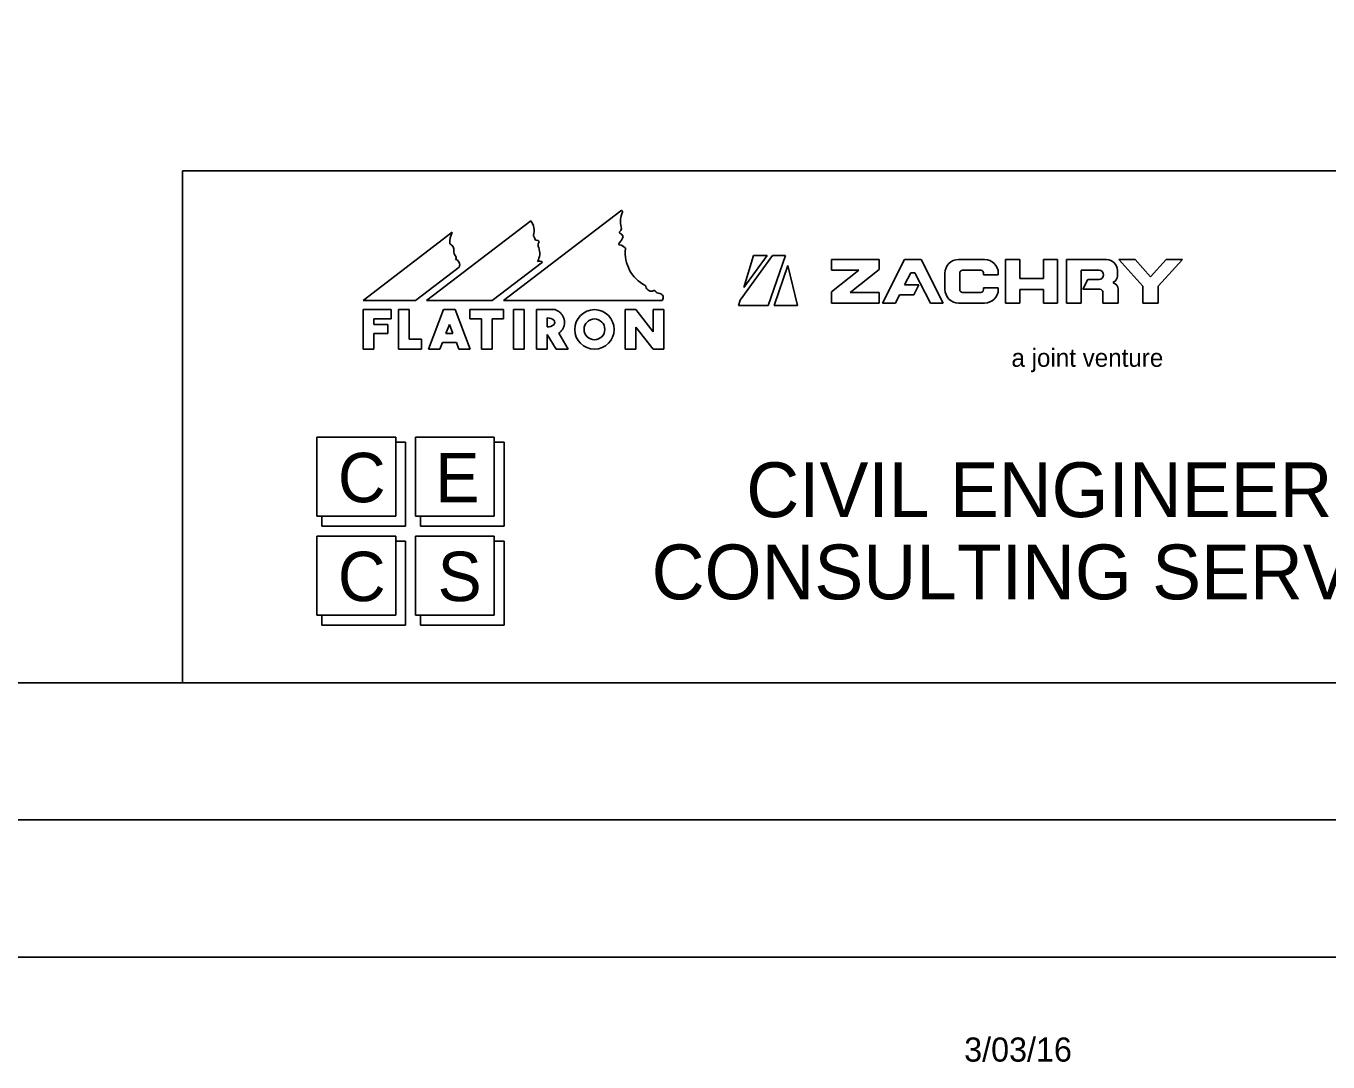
# Model space of a CAD drawing. Extents: x -2251 to 10196, y -13470 to 1199.
# Drawn here: x 1285.2 to 1522.9, y -7469.8 to -7280.7 of the extents above; entities that cross this region are included whole.
import ezdxf

# ---------------------------------------------------------------- set-up
doc = ezdxf.new("R2010")
doc.units = 0
for name, color, linetype in [('Level 3', 7, 'Continuous'), ('RD_SHT_Bndy', 7, 'Continuous'), ('RD_SHT_Iplotshp', 7, 'Continuous'), ('RD_SHT_Logo', 7, 'Continuous'), ('RD_SHT_Misc1', 7, 'Continuous'), ('RD_SHT_Snap', 7, 'Continuous'), ('RD_SHT_TX', 7, 'Continuous')]:
    doc.layers.add(name, color=color, linetype=linetype)

msp = doc.modelspace()

# ---------------------------------------------------------------- linework, layer by layer
at = {"layer": 'Level 3'}
msp.add_line((1465.07, -7363.99), (1465.07, -7363.99), dxfattribs=at)
msp.add_line((1465.07, -7363.99), (1465.07, -7363.99), dxfattribs=at)
msp.add_line((1465.07, -7363.99), (1465.07, -7363.99), dxfattribs=at)
msp.add_line((1465.07, -7363.99), (1465.07, -7363.99), dxfattribs=at)
at = {"layer": 'RD_SHT_Bndy'}
for p, q in [((103.1, -7400.65), (1778.1, -7400.65)), ((1791.65, -7425.65), (31.65, -7425.65)), ((1791.6, -7450.7), (31.6, -7450.65))]:
    msp.add_line(p, q, dxfattribs=at)
at = {"layer": 'RD_SHT_Iplotshp'}
msp.add_lwpolyline([(-3.35, -6325.65), (1796.65, -6325.65), (1796.65, -7425.65), (-3.35, -7425.65)], close=True, dxfattribs=at)
at = {"layer": 'RD_SHT_Logo'}
for p, q in [((1372.32, -7330.86), (1393.74, -7314.44)), ((1346.7, -7330.86), (1362.98, -7318.38)), ((1377.35, -7316.27), (1358.31, -7330.86)), ((1415.56, -7330.77), (1421.47, -7322.59)), ((1420.48, -7322.59), (1416.24, -7328.47)), ((1416.24, -7328.47), (1417.96, -7322.59)), ((1417.96, -7322.59), (1420.48, -7322.59)), ((1423.82, -7322.59), (1420.68, -7331.76)), ((1421.47, -7322.59), (1423.82, -7322.59)), ((1364.27, -7324.74), (1356.29, -7330.86)), ((1370.3, -7330.86), (1379.48, -7323.82)), ((1424.24, -7324.44), (1421.74, -7331.76)), ((1425.99, -7331.76), (1424.24, -7324.44)), ((1440.93, -7323.35), (1432.22, -7323.35)), ((1432.22, -7323.35), (1432.22, -7325.3)), ((1437.2, -7325.3), (1432.22, -7329.24)), ((1432.22, -7325.3), (1437.2, -7325.3)), ((1435.63, -7329.35), (1440.93, -7325.16)), ((1440.93, -7325.16), (1440.93, -7323.35)), ((1445.58, -7323.35), (1441.53, -7331.3)), ((1448.58, -7323.35), (1445.58, -7323.35)), ((1452.63, -7331.3), (1448.58, -7323.35)), ((1455.44, -7323.35), (1460.18, -7323.35)), ((1459.48, -7325.3), (1456.14, -7325.3)), ((1466.62, -7323.35), (1464.02, -7323.35)), ((1464.02, -7323.35), (1464.02, -7331.3)), ((1466.62, -7326.8), (1466.62, -7323.35)), ((1470.9, -7323.35), (1470.9, -7326.8)), ((1473.51, -7323.35), (1470.9, -7323.35)), ((1473.5, -7331.3), (1473.51, -7323.35)), ((1482.43, -7323.35), (1475.13, -7323.35)), ((1475.13, -7323.35), (1475.13, -7331.3)), ((1477.83, -7331.3), (1477.83, -7325.31)), ((1477.83, -7325.31), (1481.07, -7325.31)), ((1484.43, -7326.36), (1484.43, -7325.35)), ((1484.68, -7323.35), (1487.64, -7323.35)), ((1489.08, -7328.24), (1484.68, -7323.35)), ((1487.64, -7323.35), (1490.48, -7326.51)), ((1490.48, -7326.51), (1493.32, -7323.35)), ((1496.28, -7323.35), (1491.88, -7328.24)), ((1493.32, -7323.35), (1496.28, -7323.35)), ((1445.57, -7327.99), (1446.71, -7325.75)), ((1446.71, -7325.75), (1447.44, -7325.75)), ((1447.44, -7325.75), (1450.27, -7331.3)), ((1452.94, -7328.8), (1452.94, -7325.85)), ((1455.64, -7325.8), (1455.64, -7328.85)), ((1459.98, -7326.15), (1459.98, -7325.8)), ((1462.68, -7326.15), (1459.98, -7326.15)), ((1462.68, -7325.85), (1462.68, -7326.15)), ((1470.9, -7326.8), (1466.62, -7326.8)), ((1479.03, -7326.97), (1478.11, -7328.77)), ((1481.07, -7326.97), (1479.03, -7326.97)), ((1483.68, -7327.6), (1483.68, -7327.47)), ((1432.22, -7329.24), (1432.22, -7331.3)), ((1440.93, -7329.35), (1435.63, -7329.35)), ((1440.93, -7331.3), (1440.93, -7329.35)), ((1443.88, -7331.3), (1444.65, -7329.79)), ((1444.65, -7329.79), (1447.23, -7329.79)), ((1448.15, -7327.99), (1445.57, -7327.99)), ((1447.23, -7329.79), (1448.15, -7327.99)), ((1456.14, -7329.35), (1459.48, -7329.35)), ((1459.98, -7328.5), (1462.68, -7328.5)), ((1459.98, -7328.85), (1459.98, -7328.5)), ((1462.68, -7328.5), (1462.68, -7328.8)), ((1466.62, -7331.3), (1466.62, -7328.8)), ((1466.62, -7328.8), (1470.9, -7328.8)), ((1470.9, -7328.8), (1470.9, -7331.3)), ((1478.11, -7328.77), (1481.24, -7328.77)), ((1481.74, -7329.27), (1481.74, -7331.3)), ((1484.54, -7331.3), (1484.54, -7328.76)), ((1489.08, -7331.3), (1489.08, -7328.24)), ((1491.88, -7328.24), (1491.88, -7331.3)), ((1356.29, -7330.86), (1346.7, -7330.86)), ((1346.72, -7339.7), (1346.72, -7332.5)), ((1346.72, -7332.5), (1351.82, -7332.5)), ((1351.82, -7332.5), (1351.82, -7334.15)), ((1355.12, -7332.5), (1353.17, -7332.5)), ((1353.17, -7332.5), (1353.17, -7339.7)), ((1355.12, -7337.9), (1355.12, -7332.5)), ((1358.31, -7330.86), (1370.3, -7330.86)), ((1361.42, -7332.5), (1358.65, -7339.71)), ((1363.52, -7332.5), (1361.42, -7332.5)), ((1366.28, -7339.71), (1363.52, -7332.5)), ((1366.22, -7334.15), (1366.22, -7332.5)), ((1366.22, -7332.5), (1372.37, -7332.5)), ((1401.19, -7330.86), (1372.32, -7330.86)), ((1372.37, -7332.5), (1372.37, -7334.15)), ((1374.17, -7339.71), (1374.17, -7332.5)), ((1374.17, -7332.5), (1376.12, -7332.5)), ((1376.12, -7332.5), (1376.12, -7339.71)), ((1381.8, -7332.5), (1378.38, -7332.5)), ((1378.38, -7332.5), (1378.38, -7339.71)), ((1396.52, -7332.5), (1394.57, -7332.5)), ((1394.57, -7332.5), (1394.57, -7339.71)), ((1399.67, -7336.53), (1396.52, -7332.5)), ((1401.62, -7332.5), (1399.67, -7332.5)), ((1399.67, -7332.5), (1399.67, -7336.53)), ((1401.62, -7339.71), (1401.62, -7332.5)), ((1415.27, -7331.76), (1415.56, -7330.77)), ((1420.68, -7331.76), (1415.27, -7331.76)), ((1421.74, -7331.76), (1425.99, -7331.76)), ((1432.22, -7331.3), (1440.93, -7331.3)), ((1441.53, -7331.3), (1443.88, -7331.3)), ((1450.27, -7331.3), (1452.63, -7331.3)), ((1460.18, -7331.3), (1455.44, -7331.3)), ((1464.02, -7331.3), (1466.62, -7331.3)), ((1470.9, -7331.3), (1473.5, -7331.3)), ((1475.13, -7331.3), (1477.83, -7331.3)), ((1481.74, -7331.3), (1484.54, -7331.3)), ((1491.88, -7331.3), (1489.08, -7331.3)), ((1351.82, -7334.15), (1348.67, -7334.15)), ((1348.67, -7334.15), (1348.67, -7335.21)), ((1368.32, -7334.15), (1366.22, -7334.15)), ((1368.32, -7339.71), (1368.32, -7334.15)), ((1372.37, -7334.15), (1370.27, -7334.15)), ((1370.27, -7334.15), (1370.27, -7339.71)), ((1380.33, -7335.66), (1380.33, -7334.01)), ((1348.67, -7335.21), (1351.22, -7335.21)), ((1351.22, -7336.86), (1348.67, -7336.86)), ((1348.67, -7336.86), (1348.67, -7339.7)), ((1351.22, -7335.21), (1351.22, -7336.86)), ((1361.83, -7336.86), (1362.47, -7335.2)), ((1363.1, -7336.86), (1361.83, -7336.86)), ((1362.47, -7335.2), (1363.1, -7336.86)), ((1380.33, -7339.71), (1380.33, -7337.02)), ((1380.33, -7337.02), (1381.94, -7339.71)), ((1384.16, -7339.71), (1382.43, -7336.82)), ((1396.52, -7339.71), (1396.52, -7335.67)), ((1396.52, -7335.67), (1399.67, -7339.71)), ((1348.67, -7339.7), (1346.72, -7339.7)), ((1353.17, -7339.7), (1357.37, -7339.71)), ((1357.37, -7337.9), (1355.12, -7337.9)), ((1357.37, -7339.71), (1357.37, -7337.9)), ((1358.65, -7339.71), (1360.74, -7339.71)), ((1360.74, -7339.71), (1361.2, -7338.51)), ((1361.2, -7338.51), (1363.74, -7338.51)), ((1363.74, -7338.51), (1364.2, -7339.71)), ((1364.2, -7339.71), (1366.28, -7339.71)), ((1370.27, -7339.71), (1368.32, -7339.71)), ((1376.12, -7339.71), (1374.17, -7339.71)), ((1378.38, -7339.71), (1380.33, -7339.71)), ((1381.94, -7339.71), (1384.16, -7339.71)), ((1394.57, -7339.71), (1396.52, -7339.71)), ((1399.67, -7339.71), (1401.62, -7339.71)), ((1352.67, -7355.79), (1338.28, -7355.79)), ((1338.28, -7355.79), (1338.28, -7370.23)), ((1352.67, -7370.23), (1352.67, -7355.79)), ((1352.67, -7355.79), (1352.67, -7370.23)), ((1370.67, -7355.79), (1356.27, -7355.79)), ((1356.27, -7355.79), (1356.27, -7370.23)), ((1370.67, -7370.23), (1370.67, -7355.79)), ((1370.67, -7355.79), (1370.67, -7370.23)), ((1354.48, -7356.7), (1352.67, -7356.7)), ((1354.48, -7372.03), (1354.48, -7356.7)), ((1372.48, -7356.7), (1370.67, -7356.7)), ((1372.48, -7372.03), (1372.48, -7356.7)), ((1338.28, -7370.23), (1352.67, -7370.23)), ((1352.67, -7370.23), (1339.17, -7370.23)), ((1339.17, -7370.23), (1339.17, -7372.03)), ((1356.27, -7370.23), (1370.67, -7370.23)), ((1370.67, -7370.23), (1357.18, -7370.23)), ((1357.18, -7370.23), (1357.18, -7372.03)), ((1339.17, -7372.03), (1354.48, -7372.03)), ((1357.18, -7372.03), (1372.48, -7372.03)), ((1352.67, -7373.84), (1338.28, -7373.84)), ((1338.28, -7373.84), (1338.28, -7388.27)), ((1352.67, -7388.27), (1352.67, -7373.84)), ((1352.67, -7373.84), (1352.67, -7388.27)), ((1354.48, -7374.74), (1352.67, -7374.74)), ((1354.48, -7390.07), (1354.48, -7374.74)), ((1370.67, -7373.84), (1356.27, -7373.84)), ((1356.27, -7373.84), (1356.27, -7388.27)), ((1370.67, -7388.27), (1370.67, -7373.84)), ((1370.67, -7373.84), (1370.67, -7388.27)), ((1372.48, -7374.74), (1370.67, -7374.74)), ((1372.48, -7390.07), (1372.48, -7374.74)), ((1338.28, -7388.27), (1352.67, -7388.27)), ((1352.67, -7388.27), (1339.17, -7388.27)), ((1339.17, -7388.27), (1339.17, -7390.07)), ((1356.27, -7388.27), (1370.67, -7388.27)), ((1370.67, -7388.27), (1357.18, -7388.27)), ((1357.18, -7388.27), (1357.18, -7390.07)), ((1339.17, -7390.07), (1354.48, -7390.07)), ((1357.18, -7390.07), (1372.48, -7390.07))]:
    msp.add_line(p, q, dxfattribs=at)
for radius in [3.6, 1.9]:
    msp.add_circle((1388.95, -7336.1), radius, dxfattribs=at)
for centre, radius, start, end in [((1397.87, -7316.34), 4.17, 156.4699, 195.3053), ((1393.86, -7314.6), 0.2, 336.4699, 127.4657), ((1366.29, -7320.12), 3.74, 152.2252, 185.8662), ((1375.05, -7318.02), 2.89, 342.0343, 37.2653), ((1393.73, -7318.39), 0.2, 129.4079, 246.863), ((1393.13, -7317.66), 0.749, 309.4079, 17.0499), ((1362.1, -7321.62), 1.21, 351.6466, 67.1294), ((1377.99, -7318.97), 0.2, 162.0343, 220.8638), ((1376.86, -7319.95), 1.3, 11.8745, 40.8638), ((1378.32, -7319.64), 0.2, 191.8745, 279.8173), ((1378.44, -7320.33), 0.499, 44.4799, 99.8173), ((1379.5, -7320.72), 0.843, 144.641, 212.5499), ((1378.65, -7320.12), 0.2, 324.641, 44.4799), ((1393.57, -7320.5), 0.2, 133.0036, 262.3069), ((1391.59, -7318.37), 2.7, 313.0036, 343.6807), ((1393.31, -7322.44), 1.76, 45.283, 82.3069), ((1393.27, -7319.47), 0.973, 20.4113, 66.863), ((1364.29, -7321.94), 1, 171.6466, 221.9371), ((1363.11, -7323.01), 0.592, 327.6019, 41.9371), ((1375.8, -7322.18), 3.16, 331.2486, 18.4584), ((1394.4, -7321.33), 0.2, 353.8329, 45.283), ((1401.36, -7322.08), 6.8, 173.8329, 242.3928), ((1363.3, -7324.33), 1.05, 337.4201, 73.1261), ((1378.92, -7324.44), 0.827, 48.0701, 115.7229), ((1455.44, -7325.85), 2.5, 89.9984, 179.9984), ((1456.14, -7325.8), 0.5, 89.9984, 179.9984), ((1459.48, -7325.8), 0.5, 359.9984, 89.9984), ((1460.18, -7325.85), 2.5, 359.9984, 89.9984), ((1481.07, -7326.14), 0.831, 269.9984, 89.9984), ((1482.43, -7325.35), 2, 359.9984, 89.9984), ((1483.23, -7326.36), 1.2, 291.95, 359.9984), ((1483.34, -7328.76), 1.2, 359.9984, 73.7977), ((1398.12, -7328.28), 0.2, 9.0833, 62.3928), ((1399.35, -7328.09), 1.04, 189.0833, 295.769), ((1399.89, -7329.21), 0.2, 33.7112, 115.769), ((1400.89, -7328.54), 1.01, 213.7112, 268.6299), ((1400.86, -7329.74), 0.2, 78.9712, 88.6299), ((1400.75, -7330.3), 0.767, 320.912, 78.9712), ((1455.44, -7328.8), 2.5, 179.9984, 269.9984), ((1456.14, -7328.85), 0.5, 179.9984, 269.9984), ((1459.48, -7328.85), 0.5, 269.9984, 359.9984), ((1460.18, -7328.8), 2.5, 269.9984, 359.9984), ((1481.24, -7329.27), 0.5, 359.9984, 89.9984), ((1401.19, -7330.66), 0.2, 269.9984, 320.912)]:
    msp.add_arc(centre, radius, start, end, dxfattribs=at)
msp.add_ellipse((1380.33, -7334.83), major_axis=(1.36, 0), ratio=0.609965, start_param=4.712389, end_param=7.853982, dxfattribs=at)
msp.add_open_spline([(1382.43, -7336.82), (1382.51, -7336.76), (1382.59, -7336.7), (1382.81, -7336.49), (1382.95, -7336.34), (1383.13, -7336.07), (1383.19, -7335.97), (1383.29, -7335.77), (1383.34, -7335.66), (1383.41, -7335.44), (1383.44, -7335.32), (1383.47, -7335.08), (1383.48, -7334.96), (1383.48, -7334.71), (1383.47, -7334.59), (1383.44, -7334.35), (1383.41, -7334.23), (1383.34, -7334.01), (1383.29, -7333.9), (1383.19, -7333.7), (1383.13, -7333.6), (1382.95, -7333.33), (1382.81, -7333.18), (1382.52, -7332.91), (1382.37, -7332.8), (1382.08, -7332.63), (1381.94, -7332.56), (1381.8, -7332.5)], degree=3, dxfattribs=at)
at = {"layer": 'RD_SHT_Misc1'}
msp.add_lwpolyline([(1796.65, -7425.65), (1796.68, -6325.65), (96.68, -6325.6), (96.65, -7425.6)], close=True, dxfattribs=at)
at = {"layer": 'RD_SHT_Snap'}
msp.add_lwpolyline([(8.15, -6325.65), (1808.15, -6325.65), (1808.15, -7425.65), (8.15, -7425.65)], close=True, dxfattribs=at)
at = {"layer": 'RD_SHT_TX'}
for p, q in [((1313.76, -7400.65), (1313.76, -7307.15)), ((1313.76, -7400.65), (1313.76, -7307.15)), ((1313.76, -7307.15), (1778.1, -7307.15))]:
    msp.add_line(p, q, dxfattribs=at)

# ---------------------------------------------------------------- texts
at = {"layer": 'RD_SHT_Logo'}
msp.add_text('a joint venture', height=3.3, rotation=359.9984, dxfattribs=at).set_placement((1465.08, -7342.93))
for s, height, p in [('C', 9.02, (1342.11, -7367.66)), ('E', 9.02, (1359.9, -7367.66)), ('CIVIL ENGINEERING', 10, (1416.67, -7370.38)), ('CONSULTING SERVICES, INC.', 10, (1399.39, -7385.38)), ('C', 9.02, (1342.11, -7385.71)), ('S', 9.02, (1360.32, -7385.71))]:
    msp.add_text(s, height=height, dxfattribs=at).set_placement(p)
at = {"layer": 'RD_SHT_TX'}
msp.add_text('3/03/16', height=4.408, dxfattribs=at).set_placement((1456.45, -7469.78))

doc.saveas('drawing.dxf')
